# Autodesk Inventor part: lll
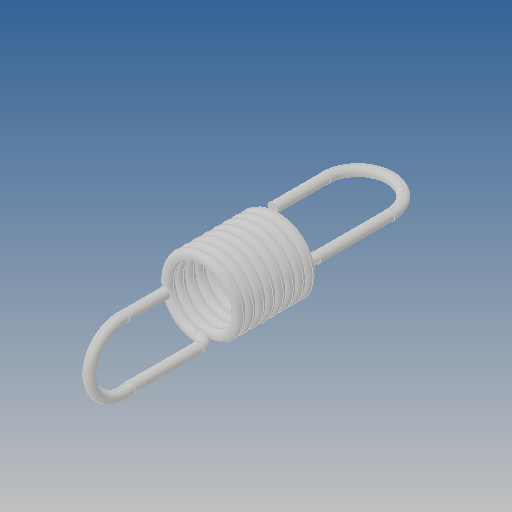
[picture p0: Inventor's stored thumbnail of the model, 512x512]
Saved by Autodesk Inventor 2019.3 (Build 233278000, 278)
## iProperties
Created: 2017-12
Part Number: lll
Material: Ogólny
Document SubType Name: Modeling
Designer: Admin
Density: 1 g/cm^3
Appearance: Domyślna
Author: Admin
Revision Number: ÈÎºÎ
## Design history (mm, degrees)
feature "É¨Ãè8"
node "Bryła1"
